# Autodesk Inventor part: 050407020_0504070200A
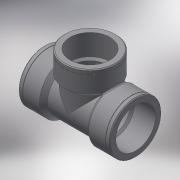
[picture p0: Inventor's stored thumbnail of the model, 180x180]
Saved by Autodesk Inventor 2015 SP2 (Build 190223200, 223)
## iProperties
Created: 2017-05
Part Number: 050407020_0504070200A
Material: Generic
Description: PLASSON THREADED TEE 2"
Document SubType Name: Modeling
Designer: KIM
Density: 1 g/cm^3
Appearance: Default
Author: KIM
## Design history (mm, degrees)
derived "050407.ipt"
feature "Solid1::050407.ipt"
tag "TaggingFeature1"
body "Solid1"
other parameters: "d0" = 65, "d2" = 0.5, "d3" = 0.5, "d4" = 73.6528, "d5" = 56.656, "d7" = 135 deg, "d8" = 34.5, "d9" = 5.75, "d19" = 1.13312, "d30" = 50.9904, "d31" = 62.3216, "d33" = 180 deg, "d39" = 0, "d45" = 0, "d46" = 62.3216, "d48" = 0, "d50" = 0, "d51" = 1.69968, "Rp_" = 56.656
